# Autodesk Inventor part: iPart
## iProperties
Shininess: 64.0
Length Units: 11269
Angle Units: 11279
Time Units: 11290
Mass Units: 11283
Length Display Precision: 3
Angle Display Precision: 2
Created: 2002-11
Part Number: iPart
Document SubType Name: Modeling
Designer: ***
Density: 1 g/cm^3
Density: 0.0
Volumn: 0.0
Area: 0.0
PropertySet Name: Model Information
Control State: 0
Master: False
Checked Out: False
Author: ***
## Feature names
1. Extrusion1
2. Hole1
3. Fillet1
